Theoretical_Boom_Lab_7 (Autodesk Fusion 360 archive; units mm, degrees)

design "Theoretical Boom Lab 7" references "Boom Anchor", "Big Dowel Quarter", "Thick Dowel", "1ThinConnector", "Thin Dowel", "2ThickConnector"
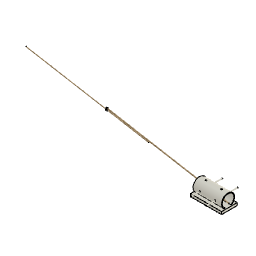
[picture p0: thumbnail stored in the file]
component_insert "Component Insert1"
component_insert "Component Insert2"
position "Position1"
component_insert "Component Insert3"
position "Position2"
component_insert "Component Insert4"
component_insert "Component Insert5"
component_insert "Component Insert6"
position "Position3"
component_insert "Component Insert11"

design "Thick Dowel"
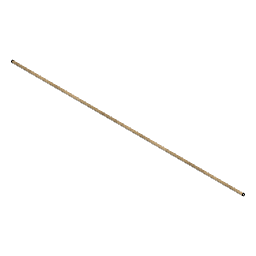
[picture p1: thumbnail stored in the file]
sketch "Sketch1" plane through (0, 0, 0) normal (1, 0, 0) x axis (0, 0, -1)
  circle C1 centre (0, 0) radius 5.5
  point P1 (0, 0)
  point P2 (0, 0)
  coincident P1 P2
  dimension "d1" diameter C1 = 11
extrude "Extrude1" new body sketch "Sketch1" along normal blind 1220

design "Boom Anchor"
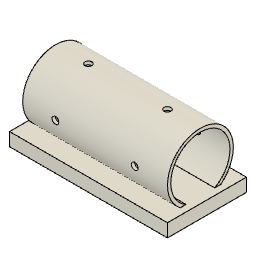
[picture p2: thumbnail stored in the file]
sketch "Sketch1" plane through (0, 0, 0) normal (0, 0, 1) x axis (1, 0, 0)
  line L1 (-152.4, 12.7) -> (152.4, 12.7)
  line L2 (-152.4, -12.7) -> (-152.4, 12.7)
  line L3 (152.4, -12.7) -> (-152.4, -12.7)
  line L4 (152.4, 12.7) -> (152.4, -12.7)
  line L5 (-152.4, -12.7) -> (152.4, 12.7)
  line L6 (152.4, -12.7) -> (-152.4, 12.7)
  point P6 (0, 0)
  point P1 (0, 0)
  point P4 (-152.4, -12.7)
  point P5 (152.4, -12.7)
  point P3 (-152.4, 12.7)
  horizontal L1
  perpendicular L1 L2
  parallel L1 L3
  parallel L2 L4
  coincident L5 P6
  coincident L6 P6
  coincident P1 P6
  dimension "d1" distance P4 P5 = 304.8
  dimension "d2" distance P3 P4 = 25.4
  dimension "d22" OffsetX = 0
  dimension "d23" OffsetY = 0
  dimension "d24" OffsetZ = 0
  dimension "d25" AngleZ = 0
  dimension "d26" OffsetX = 0
  dimension "d27" OffsetY = 0
  dimension "d28" OffsetZ = 0
  dimension "d29" AngleZ = 0
  dimension "d30" alignAngle = -90
  dimension "d31" alignOffsetX = 0
  dimension "d32" alignOffsetY = 0
  dimension "d33" alignOffsetZ = 0
extrude "Extrude1" new body sketch "Sketch1" profile of L1 L2 L3 L4 along normal blind 152.4
sketch "Sketch2" plane through (0, 0, 0) normal (1, 0, 0) x axis (0, 0, -1)
  line L1 (-152.4, 12.7) -> (0, 12.7)
  circle C1 centre (-76.2, 62.7) radius 63.5
  circle C2 centre (-76.2, 62.7) radius 57.15
  point P1 (0, 0)
  point P2 (-76.2, 62.7)
  concentric C1 C2
  dimension "d5" diameter C1 = 127
  dimension "d6" distance P1 P2 = 76.2
  dimension "d7" distance P2 L1 = 50
  dimension "d8" diameter C2 = 114.3
extrude "Extrude2" add sketch "Sketch2" distance 139.7
work_plane "WorkPlane1" sketch "Sketch3" RotateAngle 0
sketch "Sketch3" plane through (76.3154, 126.2, 76.2) normal (0, 1, 0) x axis (1, 0, 0)
  circle C1 centre (0, 0) radius 6.5
  circle C2 centre (-152.6304, 0) radius 6.5
  point P1 (0, 0)
  point P2 (0, 0)
  coincident P1 P2
  dimension "d12" diameter C1 = 13
  dimension "d13" diameter C2 = 13
extrude "Extrude3" cut sketch "Sketch3" against normal blind 10
work_plane "WorkPlane2" sketch "Sketch3" RotateAngle 90
sketch "Sketch4" plane through (-8.2615, 62.7, 139.7) normal (0, 0, 1) x axis (1, 0, 0)
  circle C1 centre (84.667, -0.1132) radius 6.5
  circle C2 centre (-68.3063, 0.0526) radius 6.5
  dimension "d18" diameter C1 = 13
  dimension "d19" diameter C2 = 13
extrude "Extrude4" cut sketch "Sketch4" + "Sketch3" profile of S1:C1 S1:C2 blind -140

design "Thin Dowel"
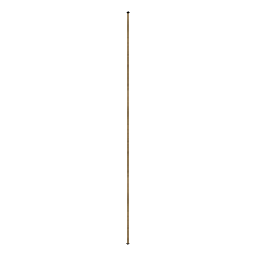
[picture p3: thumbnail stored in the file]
sketch "Sketch1" plane through (0, 0, 0) normal (0, 1, 0) x axis (1, 0, 0)
  circle C1 centre (0, 0) radius 4
  point P1 (0, 0)
  point P2 (0, 0)
  coincident P1 P2
  dimension "d1" diameter C1 = 8
extrude "Extrude1" new body sketch "Sketch1" along normal blind 1220

design "Big Dowel Quarter"
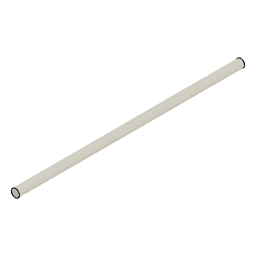
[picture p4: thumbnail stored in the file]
sketch "Sketch1" plane through (0, 0, 0) normal (0, 1, 0) x axis (1, 0, 0)
  circle C1 centre (0, 0) radius 5.5
  point P1 (0, 0)
  point P2 (0, 0)
  coincident P1 P2
  dimension "d1" diameter C1 = 11
extrude "Extrude1" new body sketch "Sketch1" along normal blind 305 (= "( 1220 / 4 ) * 1 mm")

design "1ThinConnector"
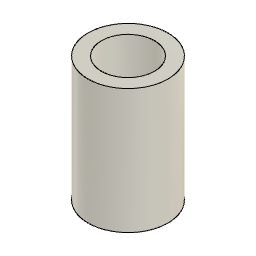
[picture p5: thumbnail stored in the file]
mesh "Mesh1" sketch "Sketch1"
sketch "Sketch1" plane through (0, 0, 0) normal (0, 0, 1) x axis (1, 0, 0)
  circle C1 centre (0, 0) radius 4.2496
  circle C2 centre (0, 0) radius 6.4031
  point P1 (0, 0)
  point P2 (0, 0)
  coincident P1 P2
  concentric C1 C2
extrude "Extrude1" new body sketch "Sketch1" along normal blind 20

design "2ThickConnector"
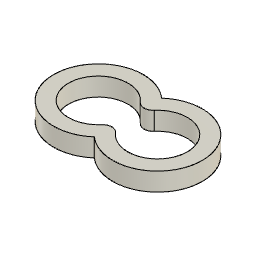
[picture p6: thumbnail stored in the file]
mesh "Mesh1" sketch "Sketch1"
sketch "Sketch1" plane through (0, 0, 0) normal (0, 0, 1) x axis (1, 0, 0)
  arc A1 centre (-6.5472, -3.7685) radius 9.8366 clockwise from (-0.055, -11.1584) to (-0.0375, 3.606)
  arc A2 centre (6.4436, -3.7839) radius 9.8293 clockwise from (-0.0375, 3.606) to (-0.055, -11.1584)
  arc A3 centre (-6.5726, -3.7822) radius 6.5479 clockwise from (-1.5902, -8.0308) to (-1.5884, 0.4643)
  arc A4 centre (6.4421, -3.7849) radius 6.5509 clockwise from (1.4562, 0.4641) to (1.4544, -8.0319)
  arc A5 centre (-0.0661, 1.7614) radius 2 clockwise from (1.4562, 0.4641) to (-1.5884, 0.4643)
  arc A6 centre (-0.0683, -9.3285) radius 2 clockwise from (-1.5902, -8.0308) to (1.4544, -8.0319)
  tangent A3 A5
  tangent A4 A5
  tangent A3 A6
  tangent A4 A6
  dimension "d1" radius A5 = 2
  dimension "d2" radius A6 = 2
extrude "Extrude1" new body sketch "Sketch1" along normal blind 4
